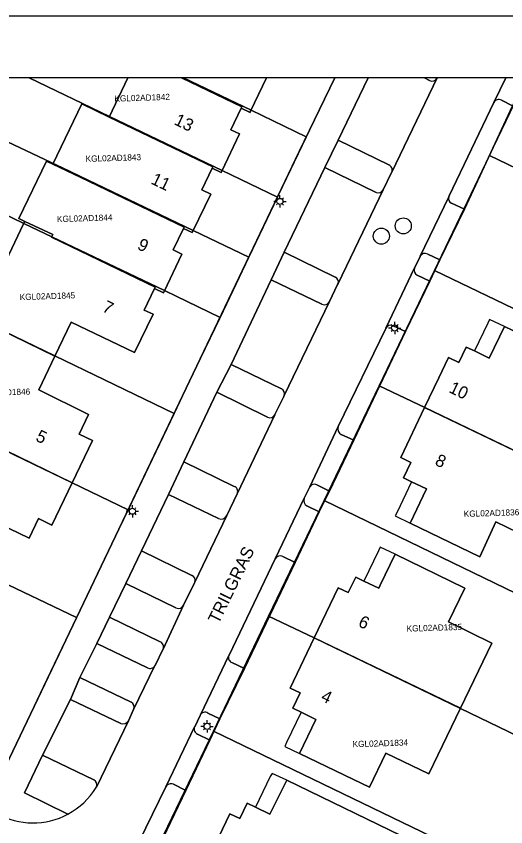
# Model space of a CAD drawing. Extents: x 124901 to 125496, y 515369 to 515789.
# Drawn here: x 125428.8 to 125468.5, y 515723.4 to 515789 of the extents above; entities that cross this region are included whole.
import ezdxf

# ---------------------------------------------------------------- set-up
doc = ezdxf.new("R2010")
doc.units = 0
for name, color, linetype in [('Alg Kaders', 7, 'Continuous'), ('Gebouw', 7, 'Continuous'), ('Inrit', 7, 'Continuous'), ('Lichtmast', 7, 'Continuous'), ('Luifel', 7, 'Continuous'), ('Onbegroeid terrein', 7, 'Continuous'), ('Parkeren', 7, 'Continuous'), ('Perceelnummers', 7, 'Continuous'), ('Perceelsgrenzen', 7, 'Continuous'), ('Putten', 7, 'Continuous'), ('Teksten', 7, 'Continuous'), ('Vegetatie', 7, 'Continuous'), ('Voetpad', 7, 'Continuous'), ('Wegen lokale weg', 7, 'Continuous')]:
    doc.layers.add(name, color=color, linetype=linetype)

msp = doc.modelspace()

# ---------------------------------------------------------------- linework, layer by layer
at = {"layer": 'Alg Kaders'}
for points in [[(125495.925, 515789.043), (124901.425, 515789.043), (124901.425, 515368.543), (125495.925, 515368.543)], [(125490.925, 515784.043), (124906.425, 515784.043), (124906.425, 515373.543), (125490.925, 515373.543)]]:
    msp.add_lwpolyline(points, close=True, dxfattribs=at)
at = {"layer": 'Gebouw'}
for points in [[(125437.855, 515784.043), (125436.334, 515780.873), (125444.745, 515776.84), (125444.691, 515776.729), (125445.412, 515776.381), (125445.466, 515776.494), (125446.915, 515779.505), (125446.2, 515779.848), (125447.035, 515781.596), (125447.087, 515781.705), (125442.212, 515784.043)], [(125442.212, 515784.043), (125447.087, 515781.705), (125447.035, 515781.596), (125447.757, 515781.251), (125447.809, 515781.359), (125449.092, 515784.043)]]:
    msp.add_lwpolyline(points, dxfattribs=at)
for points in [[(125442.357, 515771.859), (125443.078, 515771.513), (125443.131, 515771.625), (125444.575, 515774.635), (125443.845, 515774.978), (125444.691, 515776.729), (125444.745, 515776.84), (125436.334, 515780.873), (125434.119, 515781.934), (125431.786, 515777.064), (125433.999, 515776.004), (125442.411, 515771.97)], [(125440.792, 515766.758), (125442.239, 515769.763), (125441.519, 515770.114), (125442.357, 515771.859), (125442.411, 515771.97), (125433.999, 515776.004), (125431.786, 515777.064), (125431.266, 515777.313), (125429.033, 515772.652), (125429.508, 515772.425), (125431.77, 515771.355), (125431.668, 515771.141), (125440.075, 515767.102), (125440.023, 515766.994), (125440.74, 515766.65)], [(125439.9, 515764.91), (125439.184, 515765.246), (125440.023, 515766.994), (125440.075, 515767.102), (125431.668, 515771.141), (125431.77, 515771.355), (125429.508, 515772.425), (125429.412, 515772.225), (125427.025, 515767.257), (125427.582, 515766.99), (125426.263, 515764.254), (125431.944, 515761.517), (125433.254, 515764.255), (125438.397, 515761.799)], [(125434.674, 515756.78), (125430.634, 515758.779), (125431.944, 515761.517), (125426.263, 515764.254), (125424.47, 515765.108), (125422.989, 515762.047), (125423.865, 515761.623), (125421.595, 515756.902), (125421.531, 515756.769), (125423.866, 515755.644), (125423.931, 515755.778), (125433.351, 515751.249), (125435, 515754.672), (125433.913, 515755.191)], [(125474.036, 515761.202), (125468.368, 515763.905), (125467.149, 515761.349), (125465.944, 515761.928), (125465.287, 515762.243), (125464.666, 515760.997), (125463.854, 515761.39), (125463.051, 515759.754), (125461.902, 515757.347), (125473.773, 515751.642), (125473.846, 515751.794), (125471.597, 515752.882), (125474.059, 515758.021), (125472.806, 515758.621)], [(125461.902, 515757.347), (125459.969, 515753.295), (125460.778, 515752.9), (125460.183, 515751.661), (125460.857, 515751.333), (125462.05, 515750.754), (125460.727, 515747.995), (125466.392, 515745.27), (125467.689, 515748.08), (125471.243, 515746.373), (125473.773, 515751.642)], [(125416.994, 515749.573), (125424.461, 515745.935), (125425.798, 515748.707), (125429.858, 515746.762), (125430.62, 515748.357), (125431.702, 515747.826), (125433.351, 515751.249), (125423.931, 515755.778), (125423.866, 515755.644), (125421.629, 515751.05), (125418.464, 515752.591)], [(125454.903, 515742.738), (125452.959, 515738.684), (125464.81, 515732.989), (125467.35, 515738.274), (125463.846, 515739.988), (125465.172, 515742.73), (125459.518, 515745.464), (125458.303, 515742.951), (125458.19, 515742.708), (125456.982, 515743.287), (125456.319, 515743.605), (125455.706, 515742.362)], [(125457.43, 515726.593), (125458.767, 515729.357), (125462.254, 515727.67), (125464.81, 515732.989), (125452.959, 515738.684), (125451.016, 515734.63), (125451.824, 515734.252), (125451.223, 515732.994), (125451.898, 515732.671), (125453.101, 515732.095), (125451.768, 515729.332), (125452.497, 515728.979), (125456.13, 515727.222)], [(125445.793, 515719.077), (125445.396, 515718.274), (125452.124, 515715.039), (125452.514, 515715.85), (125455.767, 515714.286), (125458.406, 515719.776), (125459.488, 515719.252), (125460.923, 515722.237), (125450.736, 515727.164), (125450.732, 515727.166), (125449.352, 515724.421), (125448.194, 515724.976), (125447.53, 515725.294), (125446.933, 515724.054), (125446.122, 515724.444), (125444.011, 515720.049), (125444.814, 515719.669), (125444.773, 515719.572)]]:
    msp.add_lwpolyline(points, close=True, dxfattribs=at)
at = {"layer": 'Inrit'}
msp.add_line((125468.48, 515784.043), (125467.518, 515782.052), dxfattribs=at)
for points in [[(125468.127, 515782.235), (125469.041, 515781.795), (125470.178, 515784.043)], [(125463.861, 515774.415), (125461.551, 515769.605)], [(125465.136, 515773.418), (125464.086, 515773.899)], [(125462.159, 515769.775), (125463.143, 515769.319), (125465.136, 515773.418)], [(125461.091, 515768.655), (125458.761, 515763.765)], [(125462.318, 515767.59), (125461.312, 515768.064)], [(125459.347, 515763.978), (125460.37, 515763.52), (125462.318, 515767.59)], [(125449.184, 515756.558), (125445.073, 515758.595), (125442.407, 515752.949), (125446.485, 515750.96)], [(125446.733, 515750.412), (125449.772, 515756.77)], [(125454.914, 515755.801), (125452.594, 515750.916)], [(125453.181, 515751.096), (125454.205, 515750.585), (125456.171, 515754.701)], [(125456.171, 515754.701), (125455.157, 515755.174)], [(125452.151, 515749.997), (125449.794, 515745.094)], [(125451.403, 515744.791), (125453.358, 515748.9), (125452.363, 515749.389)], [(125450.423, 515745.295), (125451.403, 515744.791)], [(125441.759, 515741.122), (125437.689, 515743.109), (125436.364, 515740.361), (125440.473, 515738.382)], [(125440.707, 515737.78), (125442.379, 515741.335)], [(125439.442, 515736.265), (125435.346, 515738.251), (125433.967, 515735.495), (125438.115, 515733.497)], [(125446.046, 515737.263), (125443.734, 515732.452)], [(125438.327, 515732.885), (125440.053, 515736.454)], [(125447.298, 515736.218), (125446.285, 515736.686)], [(125444.327, 515732.607), (125445.324, 515732.123), (125447.298, 515736.218)], [(125443.271, 515731.487), (125440.934, 515726.623)], [(125441.544, 515726.832), (125442.553, 515726.333), (125444.512, 515730.405)], [(125444.512, 515730.405), (125443.499, 515730.906)]]:
    msp.add_lwpolyline(points, dxfattribs=at)
for centre, radius, start, end in [((125467.914, 515781.84), 0.449, 61.65094, 151.79933), ((125464.24, 515774.273), 0.405, 159.53888, 247.58), ((125461.942, 515769.381), 0.45, 61.12879, 150.11375), ((125461.51, 515768.475), 0.456, 156.77924, 244.22657), ((125459.163, 515763.571), 0.447, 65.7258, 154.22471), ((125449.369, 515756.966), 0.448, 245.63666, 334.01629), ((125455.361, 515755.614), 0.485, 157.291, 245.07766), ((125446.344, 515750.566), 0.418, 338.36166, 70.33705), ((125452.978, 515750.712), 0.435, 62.10731, 151.98837), ((125452.571, 515749.803), 0.463, 155.15456, 243.29115), ((125450.21, 515744.876), 0.47, 63.04076, 152.4023), ((125441.96, 515741.545), 0.468, 244.51005, 333.4101), ((125440.289, 515737.964), 0.456, 336.20121, 66.28143), ((125446.452, 515737.093), 0.44, 157.32988, 247.66991), ((125439.656, 515736.654), 0.444, 241.11462, 333.26209), ((125437.91, 515733.083), 0.462, 334.5971, 63.61561), ((125444.103, 515732.251), 0.421, 57.8718, 151.42501), ((125443.664, 515731.306), 0.433, 155.27487, 247.57788), ((125441.343, 515726.423), 0.456, 63.89334, 153.93193)]:
    msp.add_arc(centre, radius, start, end, dxfattribs=at)
at = {"layer": 'Lichtmast'}
for p, q in [((125450.177, 515774.338), (125450.177, 515774.538)), ((125449.877, 515774.039), (125449.677, 515774.038)), ((125449.965, 515773.826), (125449.893, 515773.755)), ((125449.965, 515774.25), (125449.895, 515774.321)), ((125450.177, 515773.738), (125450.177, 515773.538)), ((125450.389, 515774.25), (125450.46, 515774.322)), ((125450.389, 515773.826), (125450.459, 515773.755)), ((125450.477, 515774.038), (125450.677, 515774.038)), ((125459.271, 515763.998), (125459.201, 515764.069)), ((125459.483, 515764.086), (125459.483, 515764.286)), ((125459.695, 515763.998), (125459.766, 515764.07)), ((125459.183, 515763.787), (125458.983, 515763.786)), ((125459.271, 515763.574), (125459.199, 515763.503)), ((125459.483, 515763.486), (125459.483, 515763.286)), ((125459.695, 515763.574), (125459.765, 515763.503)), ((125459.783, 515763.786), (125459.983, 515763.786)), ((125438.228, 515749.254), (125438.228, 515749.454)), ((125437.928, 515748.955), (125437.728, 515748.954)), ((125438.016, 515749.166), (125437.946, 515749.237)), ((125438.44, 515749.166), (125438.511, 515749.238)), ((125438.528, 515748.954), (125438.728, 515748.954)), ((125438.016, 515748.742), (125437.944, 515748.671)), ((125438.228, 515748.654), (125438.228, 515748.454)), ((125438.44, 515748.742), (125438.51, 515748.671)), ((125444.072, 515731.737), (125444.002, 515731.808)), ((125444.284, 515731.825), (125444.284, 515732.025)), ((125444.496, 515731.737), (125444.567, 515731.809)), ((125443.984, 515731.526), (125443.784, 515731.525)), ((125444.072, 515731.313), (125444, 515731.242)), ((125444.284, 515731.225), (125444.284, 515731.025)), ((125444.496, 515731.313), (125444.566, 515731.242)), ((125444.584, 515731.525), (125444.784, 515731.525))]:
    msp.add_line(p, q, dxfattribs=at)
for centre in [(125450.177, 515774.038), (125459.483, 515763.786), (125438.228, 515748.954), (125444.284, 515731.525)]:
    msp.add_circle(centre, 0.25, dxfattribs=at)
at = {"layer": 'Luifel'}
for points in [[(125467.022, 515764.17), (125465.944, 515761.928), (125467.149, 515761.349), (125468.368, 515763.905), (125467.168, 515764.477)], [(125460.727, 515747.995), (125462.05, 515750.754), (125460.857, 515751.333), (125459.674, 515748.873), (125459.528, 515748.566)], [(125458.308, 515746.048), (125458.162, 515745.741), (125456.982, 515743.287), (125458.19, 515742.708), (125458.303, 515742.951), (125459.518, 515745.464)], [(125450.581, 515729.897), (125451.768, 515729.332), (125453.101, 515732.095), (125451.898, 515732.671), (125450.714, 515730.21)], [(125449.391, 515727.464), (125448.194, 515724.976), (125449.352, 515724.421), (125450.732, 515727.166), (125449.547, 515727.718)]]:
    msp.add_lwpolyline(points, close=True, dxfattribs=at)
at = {"layer": 'Onbegroeid terrein'}
for points in [[(125396.992, 515784.043), (125396.24, 515782.475), (125389.82, 515769.117), (125383.87, 515756.723), (125380.503, 515749.71), (125427.387, 515727.139), (125451.745, 515778.087), (125454.621, 515784.043)], [(125449.092, 515784.043), (125447.809, 515781.359), (125447.757, 515781.251), (125447.035, 515781.596), (125446.2, 515779.848), (125446.915, 515779.505), (125445.466, 515776.494), (125445.412, 515776.381), (125444.691, 515776.729), (125443.845, 515774.978), (125444.575, 515774.635), (125443.131, 515771.625), (125443.078, 515771.513), (125442.357, 515771.859), (125441.519, 515770.114), (125442.239, 515769.763), (125440.792, 515766.758), (125440.74, 515766.65), (125440.023, 515766.994), (125439.184, 515765.246), (125439.9, 515764.91), (125438.397, 515761.799), (125433.254, 515764.255), (125431.944, 515761.517), (125430.634, 515758.779), (125434.674, 515756.78), (125433.913, 515755.191), (125435, 515754.672), (125433.351, 515751.249), (125431.702, 515747.826), (125430.62, 515748.357), (125429.858, 515746.762), (125425.798, 515748.707)], [(125427.025, 515767.257), (125429.412, 515772.225), (125429.508, 515772.425), (125429.033, 515772.652), (125431.266, 515777.313), (125431.786, 515777.064), (125434.119, 515781.934), (125436.334, 515780.873), (125437.855, 515784.043)], [(125470.178, 515784.043), (125469.041, 515781.795), (125465.136, 515773.418), (125463.143, 515769.319), (125462.318, 515767.59), (125460.37, 515763.52), (125456.171, 515754.701), (125454.205, 515750.585), (125453.358, 515748.9), (125451.403, 515744.791), (125447.298, 515736.218), (125445.324, 515732.123), (125444.512, 515730.405), (125442.553, 515726.333), (125439.467, 515719.919), (125461.302, 515709.415), (125461.108, 515708.964), (125462.592, 515708.439), (125490.925, 515767.272)]]:
    msp.add_lwpolyline(points, dxfattribs=at)
for points in [[(125468.368, 515763.905), (125474.036, 515761.202), (125472.806, 515758.621), (125474.059, 515758.021), (125471.597, 515752.882), (125473.846, 515751.794), (125473.773, 515751.642), (125471.243, 515746.373), (125467.689, 515748.08), (125466.392, 515745.27), (125460.727, 515747.995), (125462.05, 515750.754), (125460.857, 515751.333), (125460.183, 515751.661), (125460.778, 515752.9), (125459.969, 515753.295), (125461.902, 515757.347), (125463.051, 515759.754), (125463.854, 515761.39), (125464.666, 515760.997), (125465.287, 515762.243), (125465.944, 515761.928), (125467.149, 515761.349)], [(125458.767, 515729.357), (125457.43, 515726.593), (125456.13, 515727.222), (125452.497, 515728.979), (125451.768, 515729.332), (125453.101, 515732.095), (125451.898, 515732.671), (125451.223, 515732.994), (125451.824, 515734.252), (125451.016, 515734.63), (125452.959, 515738.684), (125454.903, 515742.738), (125455.706, 515742.362), (125456.319, 515743.605), (125456.982, 515743.287), (125458.19, 515742.708), (125458.303, 515742.951), (125459.518, 515745.464), (125465.172, 515742.73), (125463.846, 515739.988), (125467.35, 515738.274), (125464.81, 515732.989), (125462.254, 515727.67)], [(125445.396, 515718.274), (125445.793, 515719.077), (125444.773, 515719.572), (125444.814, 515719.669), (125444.011, 515720.049), (125446.122, 515724.444), (125446.933, 515724.054), (125447.53, 515725.294), (125448.194, 515724.976), (125449.352, 515724.421), (125450.732, 515727.166), (125450.736, 515727.164), (125460.923, 515722.237), (125459.488, 515719.252), (125458.406, 515719.776), (125455.767, 515714.286), (125452.514, 515715.85), (125452.124, 515715.039)]]:
    msp.add_lwpolyline(points, close=True, dxfattribs=at)
at = {"layer": 'Parkeren'}
for p, q in [((125459.248, 515776.417), (125462.926, 515784.043)), ((125462.3, 515783.841), (125461.89, 515784.043))]:
    msp.add_line(p, q, dxfattribs=at)
for points in [[(125457.324, 515784.043), (125454.909, 515779.003), (125459.006, 515777.002)], [(125457.968, 515774.773), (125453.826, 515776.791), (125450.532, 515769.941)], [(125454.893, 515767.39), (125458.559, 515774.988)], [(125450.532, 515769.941), (125454.655, 515767.911)], [(125453.578, 515765.708), (125449.47, 515767.698), (125446.239, 515760.829), (125450.303, 515758.852)], [(125450.521, 515758.311), (125454.195, 515765.928)], [(125445.206, 515748.367), (125441.161, 515750.305), (125438.963, 515745.749)], [(125443.274, 515743.199), (125445.873, 515748.6)], [(125438.963, 515745.749), (125443.051, 515743.757)], [(125437.278, 515731.766), (125433.219, 515733.713), (125430.942, 515729.185)], [(125435.312, 515726.609), (125437.906, 515731.983)], [(125430.942, 515729.185), (125435.094, 515727.193)]]:
    msp.add_lwpolyline(points, dxfattribs=at)
for centre, radius, start, end in [((125462.507, 515784.269), 0.476, 244.1842, 331.58795), ((125458.841, 515776.591), 0.442, 336.78615, 68.16118), ((125458.147, 515775.2), 0.463, 247.24134, 332.74044), ((125454.502, 515767.526), 0.414, 340.73798, 68.36517), ((125453.773, 515766.135), 0.47, 245.41613, 333.83268), ((125450.123, 515758.465), 0.426, 338.79742, 65.09726), ((125445.422, 515748.82), 0.502, 244.4921, 334.01911), ((125442.866, 515743.36), 0.438, 338.52695, 65.04046), ((125437.469, 515732.23), 0.502, 247.60616, 330.51814), ((125434.903, 515726.789), 0.447, 336.245, 64.69497)]:
    msp.add_arc(centre, radius, start, end, dxfattribs=at)
at = {"layer": 'Perceelsgrenzen'}
for points in [[(125429.866, 515784.043), (125436.361, 515780.929), (125445.494, 515776.552), (125449.979, 515774.394), (125447.653, 515769.528), (125443.16, 515771.683), (125434.027, 515776.061), (125433.125, 515776.493), (125428.096, 515778.871), (125427.199, 515779.303), (125424.231, 515780.744), (125425.42, 515783.225), (125425.812, 515784.043)], [(125454.62, 515784.043), (125454.618, 515784.038), (125453.774, 515782.289), (125452.319, 515779.278), (125452.303, 515779.244), (125450.064, 515774.571), (125449.979, 515774.394), (125447.653, 515769.528), (125447.624, 515769.467), (125445.325, 515764.648), (125445.273, 515764.539), (125442.991, 515759.777), (125441.604, 515756.876), (125439.52, 515752.517), (125437.872, 515749.069), (125435.948, 515745.045), (125433.703, 515740.35), (125431.007, 515734.711), (125427.387, 515727.139)], [(125442.374, 515784.043), (125447.839, 515781.421), (125452.319, 515779.278), (125452.303, 515779.244), (125450.064, 515774.571), (125449.979, 515774.394), (125445.494, 515776.552), (125436.361, 515780.929), (125429.866, 515784.043)], [(125490.925, 515767.272), (125490.581, 515766.558), (125486.079, 515757.21), (125481.589, 515747.886), (125477.083, 515738.53), (125472.603, 515729.228), (125468.102, 515719.881), (125462.723, 515708.711), (125439.425, 515719.965), (125444.794, 515731.147), (125449.264, 515740.456), (125453.764, 515749.828), (125458.221, 515759.111), (125462.706, 515768.452), (125467.174, 515777.757), (125470.192, 515784.043)], [(125454.62, 515784.043), (125454.618, 515784.038), (125453.774, 515782.289), (125452.319, 515779.278), (125447.839, 515781.421), (125442.374, 515784.043)], [(125490.925, 515767.272), (125490.581, 515766.558), (125470.865, 515775.99), (125467.174, 515777.757), (125470.192, 515784.043)]]:
    msp.add_lwpolyline(points, dxfattribs=at)
for points in [[(125445.325, 515764.648), (125440.822, 515766.82), (125429.426, 515772.254), (125421.905, 515775.893), (125423.042, 515778.262), (125424.219, 515780.719), (125424.231, 515780.744), (125427.199, 515779.303), (125428.096, 515778.871), (125433.125, 515776.493), (125434.027, 515776.061), (125443.16, 515771.683), (125447.653, 515769.528), (125447.624, 515769.467)], [(125462.706, 515768.452), (125467.174, 515777.757), (125470.865, 515775.99), (125490.581, 515766.558), (125486.079, 515757.21)], [(125441.604, 515756.876), (125426.263, 515764.254), (125418.169, 515768.109), (125421.905, 515775.893), (125429.426, 515772.254), (125440.822, 515766.82), (125445.325, 515764.648), (125445.273, 515764.539), (125442.991, 515759.777)], [(125486.079, 515757.21), (125481.589, 515747.886), (125473.773, 515751.642), (125461.911, 515757.343), (125458.221, 515759.111), (125462.706, 515768.452)], [(125437.872, 515749.069), (125433.351, 515751.249), (125421.613, 515756.939), (125414.461, 515760.383), (125418.144, 515768.057), (125418.169, 515768.109), (125426.263, 515764.254), (125441.604, 515756.876), (125439.52, 515752.517)], [(125433.703, 515740.35), (125410.215, 515751.536), (125410.278, 515751.668), (125414.442, 515760.344), (125414.461, 515760.383), (125421.613, 515756.939), (125433.351, 515751.249), (125437.872, 515749.069), (125435.948, 515745.045)], [(125481.589, 515747.886), (125477.083, 515738.53), (125453.764, 515749.828), (125458.221, 515759.111), (125461.911, 515757.343), (125473.773, 515751.642)], [(125404.72, 515740.089), (125410.215, 515751.536), (125433.703, 515740.35), (125431.007, 515734.711), (125427.387, 515727.139), (125413.755, 515733.701), (125414.614, 515735.357)], [(125477.083, 515738.53), (125472.603, 515729.228), (125464.804, 515732.977), (125452.96, 515738.684), (125449.264, 515740.456), (125453.764, 515749.828)], [(125472.603, 515729.228), (125468.102, 515719.881), (125444.794, 515731.147), (125449.264, 515740.456), (125452.96, 515738.684), (125464.804, 515732.977)], [(125462.723, 515708.711), (125439.425, 515719.965), (125444.794, 515731.147), (125468.102, 515719.881)]]:
    msp.add_lwpolyline(points, close=True, dxfattribs=at)
at = {"layer": 'Putten'}
for centre in [(125460.18, 515772.06), (125458.4, 515771.23)]:
    msp.add_circle(centre, 0.65, dxfattribs=at)
at = {"layer": 'Vegetatie'}
msp.add_line((125461.89, 515784.043), (125462.3, 515783.841), dxfattribs=at)
for points in [[(125464.086, 515773.899), (125465.136, 515773.418), (125469.041, 515781.795), (125468.127, 515782.235)], [(125467.518, 515782.052), (125463.893, 515774.482), (125463.861, 515774.415)], [(125459.006, 515777.002), (125454.909, 515779.003), (125453.826, 515776.791), (125457.968, 515774.773)], [(125458.559, 515774.988), (125459.231, 515776.382), (125459.248, 515776.417)], [(125454.655, 515767.911), (125450.532, 515769.941), (125449.47, 515767.698), (125453.578, 515765.708)], [(125461.312, 515768.064), (125462.318, 515767.59), (125463.143, 515769.319), (125462.159, 515769.775)], [(125461.551, 515769.605), (125461.536, 515769.576), (125461.106, 515768.686)], [(125461.106, 515768.686), (125461.091, 515768.655)], [(125454.195, 515765.928), (125454.852, 515767.304), (125454.893, 515767.39)], [(125455.157, 515755.174), (125456.171, 515754.701), (125460.37, 515763.52), (125459.347, 515763.978)], [(125458.761, 515763.765), (125458.759, 515763.761), (125454.914, 515755.801)], [(125450.303, 515758.852), (125446.239, 515760.829), (125445.073, 515758.595), (125449.184, 515756.558)], [(125449.772, 515756.77), (125449.775, 515756.776), (125450.492, 515758.252), (125450.521, 515758.311)], [(125446.485, 515750.96), (125442.407, 515752.949), (125441.161, 515750.305), (125445.206, 515748.367)], [(125452.594, 515750.916), (125452.576, 515750.879), (125452.151, 515749.997)], [(125453.358, 515748.9), (125454.205, 515750.585), (125453.181, 515751.096)], [(125445.873, 515748.6), (125445.874, 515748.603), (125446.709, 515750.362), (125446.733, 515750.412)], [(125452.363, 515749.389), (125453.358, 515748.9)], [(125443.051, 515743.757), (125438.963, 515745.749), (125437.689, 515743.109), (125441.759, 515741.122)], [(125449.794, 515745.094), (125446.066, 515737.305), (125446.046, 515737.263)], [(125446.285, 515736.686), (125447.298, 515736.218), (125451.403, 515744.791), (125450.423, 515745.295)], [(125442.379, 515741.335), (125443.246, 515743.141), (125443.274, 515743.199)], [(125440.473, 515738.382), (125436.364, 515740.361), (125435.346, 515738.251), (125439.442, 515736.265)], [(125440.053, 515736.454), (125440.059, 515736.467), (125440.697, 515737.758), (125440.707, 515737.78)], [(125438.115, 515733.497), (125433.967, 515735.495), (125433.219, 515733.713)], [(125433.219, 515733.713), (125437.278, 515731.766)], [(125437.906, 515731.983), (125438.327, 515732.885)], [(125443.734, 515732.452), (125443.715, 515732.413), (125443.277, 515731.499), (125443.271, 515731.487)], [(125443.499, 515730.906), (125444.512, 515730.405), (125445.324, 515732.123), (125444.327, 515732.607)], [(125435.094, 515727.193), (125430.942, 515729.185), (125429.483, 515726.15), (125433.003, 515724.418)], [(125435.298, 515726.579), (125435.312, 515726.609)], [(125440.934, 515726.623), (125438.785, 515722.195)], [(125461.302, 515709.415), (125439.467, 515719.919), (125442.553, 515726.333), (125441.544, 515726.832)]]:
    msp.add_lwpolyline(points, dxfattribs=at)
for centre, radius, start, end in [((125462.507, 515784.269), 0.476, 244.1842, 331.58795), ((125467.914, 515781.84), 0.449, 61.65094, 151.79933), ((125458.841, 515776.591), 0.442, 336.78615, 68.16118), ((125458.147, 515775.2), 0.463, 247.24134, 332.74044), ((125464.24, 515774.273), 0.405, 159.53888, 247.58), ((125461.942, 515769.381), 0.45, 61.12879, 150.11375), ((125461.51, 515768.475), 0.456, 156.77924, 244.22657), ((125454.502, 515767.526), 0.414, 340.73798, 68.36517), ((125453.773, 515766.135), 0.47, 245.41613, 333.83268), ((125459.163, 515763.571), 0.447, 65.7258, 154.22471), ((125450.123, 515758.465), 0.426, 338.79742, 65.09726), ((125449.369, 515756.966), 0.448, 245.63666, 334.01629), ((125455.361, 515755.614), 0.485, 157.291, 245.07766), ((125446.344, 515750.566), 0.418, 338.36166, 70.33705), ((125452.978, 515750.712), 0.435, 62.10731, 151.98837), ((125452.571, 515749.803), 0.463, 155.15456, 243.29115), ((125445.422, 515748.82), 0.502, 244.4921, 334.01911), ((125450.21, 515744.876), 0.47, 63.04076, 152.4023), ((125442.866, 515743.36), 0.438, 338.52695, 65.04046), ((125441.96, 515741.545), 0.468, 244.51005, 333.4101), ((125440.289, 515737.964), 0.456, 336.20121, 66.28143), ((125446.452, 515737.093), 0.44, 157.32988, 247.66991), ((125439.656, 515736.654), 0.444, 241.11462, 333.26209), ((125437.91, 515733.083), 0.462, 334.5971, 63.61561), ((125444.103, 515732.251), 0.421, 57.8718, 151.42501), ((125437.469, 515732.23), 0.502, 247.60616, 330.51814), ((125443.664, 515731.306), 0.433, 155.27487, 247.57788), ((125434.903, 515726.789), 0.447, 336.245, 64.69497), ((125430.141, 515729.756), 6.057, 298.19401, 328.36105), ((125441.343, 515726.423), 0.456, 63.89334, 153.93193)]:
    msp.add_arc(centre, radius, start, end, dxfattribs=at)
at = {"layer": 'Voetpad'}
for points in [[(125454.621, 515784.043), (125451.745, 515778.087), (125427.387, 515727.139), (125380.503, 515749.71), (125378.719, 515750.547), (125378.28, 515749.612)], [(125433.003, 515724.418), (125429.483, 515726.15), (125430.942, 515729.185), (125433.219, 515733.713), (125433.967, 515735.495), (125435.346, 515738.251), (125436.364, 515740.361), (125437.689, 515743.109), (125438.963, 515745.749), (125441.161, 515750.305), (125442.407, 515752.949), (125445.073, 515758.595), (125446.239, 515760.829), (125449.47, 515767.698), (125450.532, 515769.941), (125453.826, 515776.791), (125454.909, 515779.003), (125457.324, 515784.043)]]:
    msp.add_lwpolyline(points, dxfattribs=at)
msp.add_arc((125430.155, 515729.757), 6.051, 241.26695, 298.0762, dxfattribs=at)
at = {"layer": 'Wegen lokale weg'}
for points in [[(125462.926, 515784.043), (125459.248, 515776.417), (125459.231, 515776.382), (125458.559, 515774.988), (125454.893, 515767.39), (125454.852, 515767.304), (125454.195, 515765.928), (125450.521, 515758.311), (125450.492, 515758.252), (125449.775, 515756.776), (125449.772, 515756.77), (125446.733, 515750.412), (125446.709, 515750.362), (125445.874, 515748.603), (125445.873, 515748.6), (125443.274, 515743.199), (125443.246, 515743.141), (125442.379, 515741.335), (125440.707, 515737.78), (125440.697, 515737.758), (125440.059, 515736.467), (125440.053, 515736.454), (125438.327, 515732.885), (125437.906, 515731.983), (125435.312, 515726.609), (125435.298, 515726.579)], [(125461.091, 515768.655), (125461.106, 515768.686), (125461.536, 515769.576), (125461.551, 515769.605), (125463.861, 515774.415), (125463.893, 515774.482), (125467.518, 515782.052), (125468.48, 515784.043)], [(125438.785, 515722.195), (125440.934, 515726.623), (125443.271, 515731.487), (125443.277, 515731.499), (125443.715, 515732.413), (125443.734, 515732.452), (125446.046, 515737.263), (125446.066, 515737.305), (125449.794, 515745.094), (125452.151, 515749.997), (125452.576, 515750.879), (125452.594, 515750.916), (125454.914, 515755.801), (125458.759, 515763.761), (125458.761, 515763.765), (125461.091, 515768.655)]]:
    msp.add_lwpolyline(points, dxfattribs=at)
for centre, radius, start, end in [((125430.141, 515729.756), 6.057, 298.19401, 328.36105), ((125430.155, 515729.757), 6.051, 241.26695, 298.0762)]:
    msp.add_arc(centre, radius, start, end, dxfattribs=at)

# ---------------------------------------------------------------- texts
at = {"layer": 'Perceelnummers'}
for s, rotation, p in [('KGL02AD1842', 1.83316, (125436.776, 515782.119)), ('KGL02AD1843', 1.83313, (125434.439, 515777.241)), ('KGL02AD1844', 1.83311, (125432.122, 515772.361)), ('KGL02AD1845', 1.83307, (125429.1, 515766.049)), ('KGL02AD1846', 1.83303, (125425.457, 515758.254)), ('KGL02AD1836', 1.83349, (125465.087, 515748.485)), ('KGL02AD1835', 1.83344, (125460.454, 515739.193)), ('KGL02AD1834', 1.83339, (125456.075, 515729.833))]:
    msp.add_text(s, height=0.5, rotation=rotation, dxfattribs=at).set_placement(p)
at = {"layer": 'Teksten'}
for s, rotation, p in [('13', 334.4, (125441.536, 515780.309)), ('11', 334.4, (125439.656, 515775.509)), ('9', 334.4, (125438.554, 515770.213)), ('7', 334.3, (125435.715, 515765.174)), ('10', 334.4, (125463.798, 515758.614)), ('5', 334.3, (125430.315, 515754.694)), ('8', 334.5, (125462.671, 515752.737)), ('TRILGRAS', 63.9, (125445.202, 515739.762)), ('6', 334.4, (125456.452, 515739.668)), ('4', 334.4, (125453.427, 515733.642))]:
    msp.add_text(s, height=1, rotation=rotation, dxfattribs=at).set_placement(p)

doc.saveas('drawing.dxf')
